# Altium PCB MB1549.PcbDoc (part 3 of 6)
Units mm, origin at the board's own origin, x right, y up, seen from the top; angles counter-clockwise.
Board outline 70 x 133.34 mm, 6 copper layers (Top Layer, Signal Layer 1, Signal Layer 2, Signal Layer 3, Signal Layer 4, Bottom Layer), stack 1.57 mm thick; 289 components, 250 nets, 1288 pads, 875 vias.
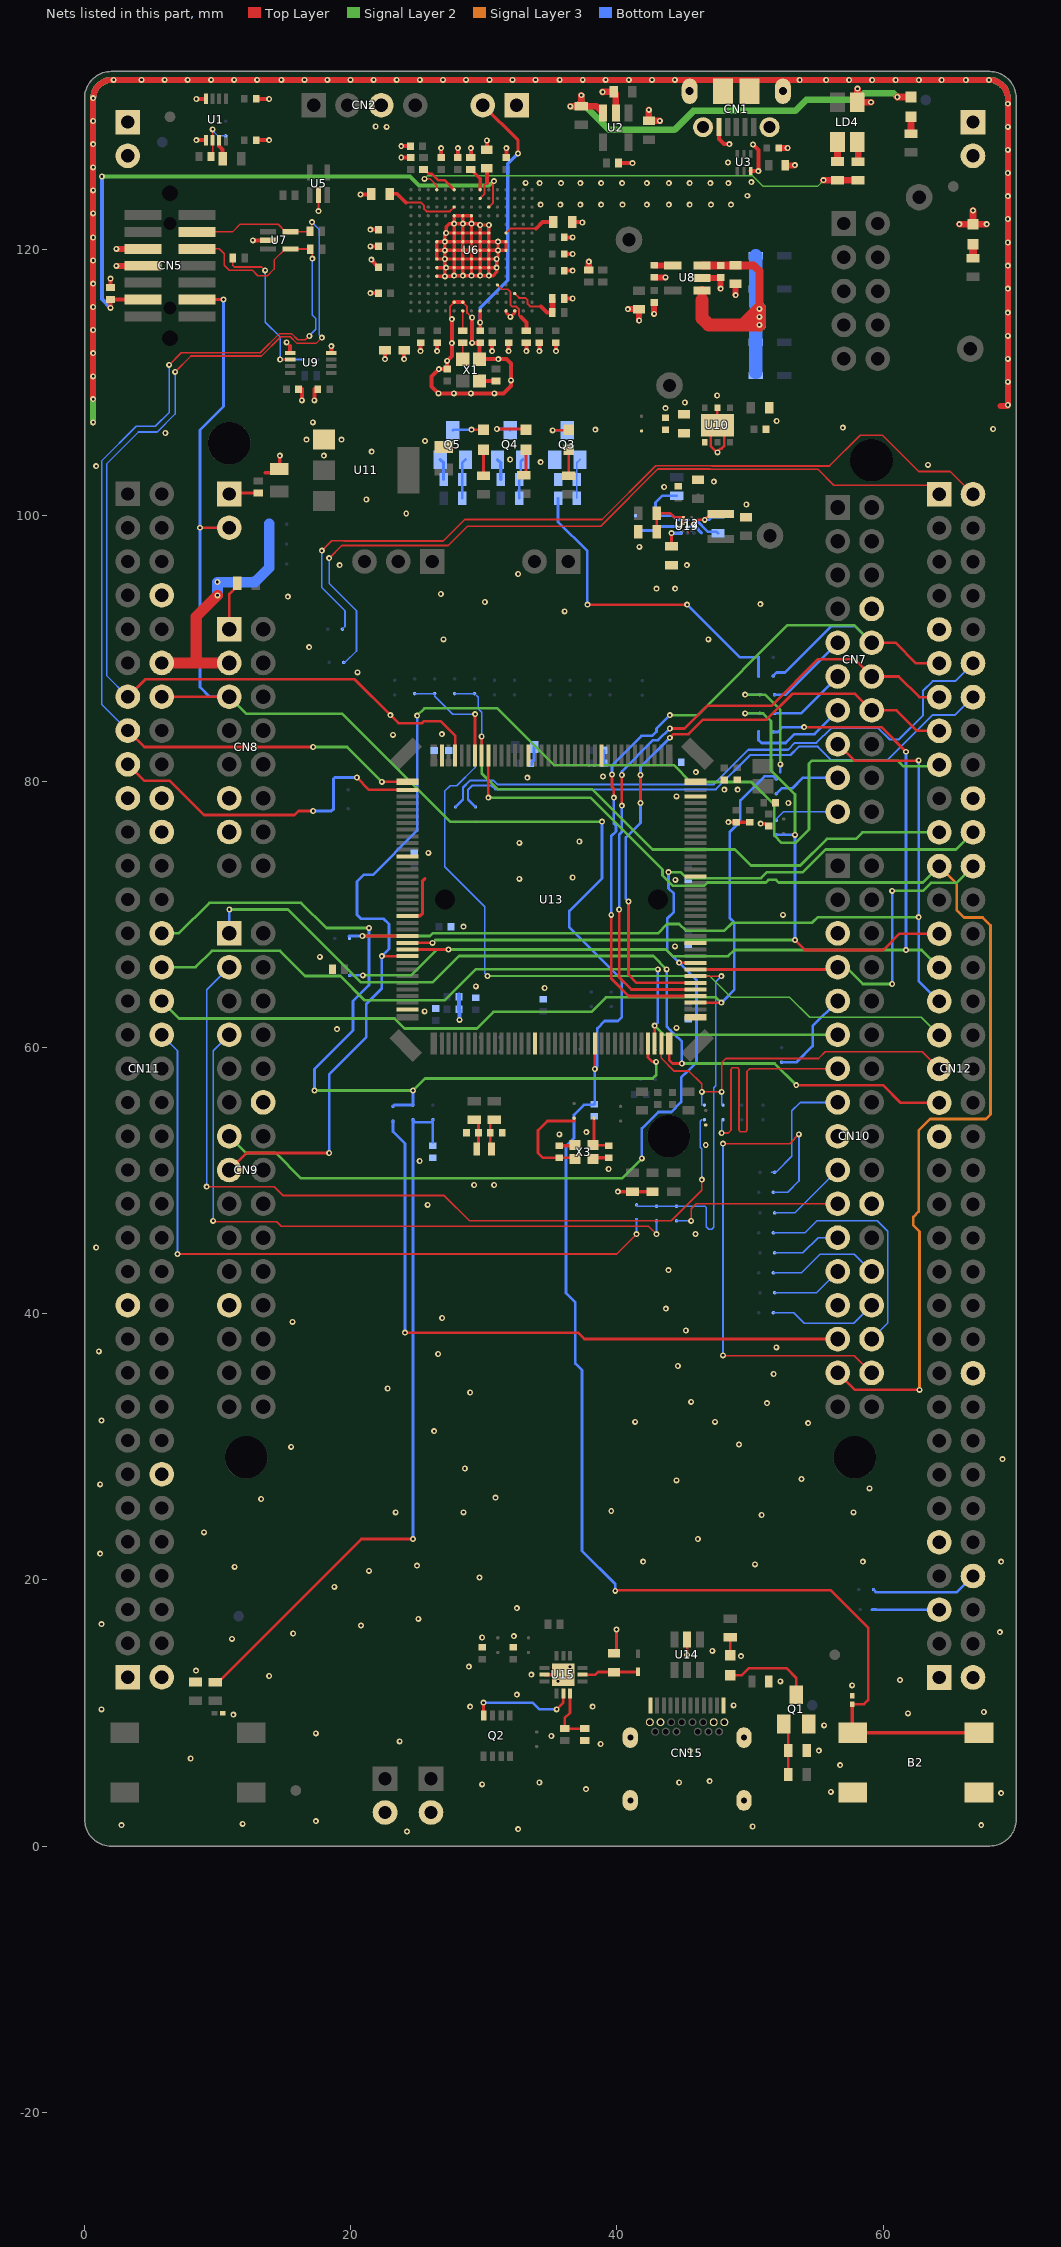
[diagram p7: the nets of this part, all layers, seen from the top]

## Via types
v1: diameter 0.45, hole 0.2, Top Layer to Bottom Layer, tented both sides, 875 vias

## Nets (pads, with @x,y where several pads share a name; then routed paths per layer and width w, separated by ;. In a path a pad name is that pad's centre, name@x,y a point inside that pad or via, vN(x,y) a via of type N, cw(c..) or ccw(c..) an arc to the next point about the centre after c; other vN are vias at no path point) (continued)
GND: B2.3 B2.4 C1.1 C2.1 C3.1 C4.2 C5.1 C6.1 C7.1 C8.1 C9.1 C10.1 C11.1 C12.1 C13.1 C14.1 C15.1 C16.1 C17.1 C18.1 C19.1 C20.1 C21.1 C22.1 C23.1 C24.1 C25.1 C26.1 C27.1 C28.1 C29.1 C30.1 C31.1 C32.1 C33.1 C34.1 C35.1 C36.2 C37.1 C38.1 C39.1 C40.1 C41.1 C42.1 C43.1 C44.1 C45.1 C46.1 C47.1 C48.1 C49.1 C50.1 C51.1 C52.1 C57.2 C58.2 C59.2 C60.2 C61.1 C62.1 C63.1 C64.1 C66.1 C67.1 C68.1 C69.1 C70.1 C71.1 C72.1 C73.1 C74.1 C75.1 C76.1 C77.1 C78.1 C79.1 C80.1 C81.1 C82.1 C83.1 C84.1 CN1.5 CN1.6 CN1.7 CN1.8 CN1.9 CN1.10 CN1.11 CN2.3 CN3.1 CN3.2 CN4.1 CN4.2 CN5.5 CN5.7 CN7.8 CN8.11 CN8.13 CN9.12 CN9.23 CN10.5 CN10.17 CN10.22 CN10.27 CN11.8 CN11.19 CN11.20 CN11.22 CN11.49 CN11.60 CN12.9 CN12.20 CN12.39 CN12.54 CN12.63 CN13.1 CN13.2 CN14.1 CN14.2 CN15.A1 CN15.A12 CN15.B1 CN15.B12 CN15.SH1 CN15.SH2 CN15.SH3 CN15.SH4 JP1.1 JP7.2 JP8.2 LD4.1 LD5.2 Q1.2 Q3.2 Q4.2 Q5.2 R6.1 R9.2 R15.1 R17.1 R18.2 R21.1 R28.2 R29.2 R31.2 R34.1 R38.1 R41.1 R42.1 R45.1 R46.1 R47.1 SB7.1 SB15.1 U1.4 U1.5 U2.2 U3.3 U4.2 U5.2 U6.D5 U6.D6 U6.D7 U6.D8 U6.D9 U6.F2 U6.F6 U6.F7 U6.F8 U6.F9 U6.F10 U6.F12 U6.G2 U6.G6 U6.G7 U6.G8 U6.G9 U6.G10 U6.G12 U6.H6 U6.H7 U6.H8 U6.H9 U6.H10 U6.H12 U6.J6 U6.J7 U6.J8 U6.J9 U6.J10 U6.K6 U6.K7 U6.K8 U6.K9 U6.K10 U6.M1 U6.M8 U6.M9 U6.N1 U7.2 U8.2 U9.4 U9.5 U10.2 U10.EP U11.1 U12.D2 U13.16 U13.37 U13.48 U13.58 U13.70 U13.72 U13.83 U13.94 U13.107 U13.120 U13.129 U13.143 U14.2 U15.2 U15.13 U16.2 U17.2 U18.2 U19.B1 U19.B2 X1.2 X3.2 X3.4 | length 573.6
  Top Layer w0.12: v1(17.575,122.85) U5.2@17.575,124.05 ; 45.307,98.662 U12.D2@45.307,99.106
  Top Layer w0.15: v1@27.129,118.604 27.148,118.623 v1@27.15,118.625 ; v1(27.591,114.729) 27.441,114.879 27.441,115.679 U6.F2@27.766,116.004 ; U6.G2@28.416,116.004 28.741,115.679 28.741,115.204 29.091,114.854 v1(29.116,114.854)
  Top Layer w0.2: v1(45.27,14.381) U14.2@45.27,15.531 U14.2@45.27,14.986 ; U10.2@47.545,108.071 U10.EP@47.545,106.771 ; v1(47.55,104.725) v1@47.505,104.725 ; v1@47.505,104.725 47.781,105.001 47.861,105.001 48.05,105.19 48.05,106.266 U10.EP@47.545,106.771 ; v1@47.505,104.725 47.05,105.18 47.05,106.276 U10.EP@47.545,106.771
  Top Layer w0.25: 13.57,103.181 14.343,103.181 14.67,103.508 v1(14.67,104.481) ; U13.129@24.462,69.871 24.487,69.896 25.224,69.896 25.382,70.055 25.382,72.507 25.575,72.7 ; U6.D5@26.466,117.954 v1(27.066,117.954) ; U6.D6@26.466,118.604 v1@27.129,118.604 ; U6.M1@31.666,115.354 31.666,115.229 v1(31.991,114.904) 32.316,115.229 U6.N1@32.316,115.354 ; U15.2@34.545,12.881 U15.13@35.97,12.881 ; C59.2@35.67,52.631 36.82,52.631 X3.4@36.87,52.681 ; X3.2@38.17,51.681 38.22,51.731 C60.2@39.37,51.731 ; C64.1@39.77,14.481 39.97,14.681 v1(39.97,16.281) ; v1(40.07,49.181) R34.1@41.17,49.181 C61.1@42.67,49.181 ; v1(48.373,76.942) 48.96,76.942 C50.1@48.97,76.931 C51.1@49.97,76.931 ; v1(50.801,76.829) 51.121,76.829 51.3,76.65 C52.1@51.35,76.65 ; U6.D8@26.466,119.904 U6.D9@26.466,120.554 v1(27.066,120.554) ; U6.D8@26.466,119.904 U6.D7@26.466,119.254 v1(27.066,119.254) ; U6.D8@26.466,119.904 v1(27.066,119.904) ; v1(27.066,117.954) 27.716,117.954 v1(27.766,118.004) ; v1(27.066,117.954) 27.066,118.504 v1(27.166,118.604) ; v1(27.066,119.254) 27.066,118.704 27.148,118.623 v1(27.166,118.604) ; v1(27.066,119.254) v1(27.066,119.904) ; v1(27.066,119.254) U6.F7@27.766,119.254 ; v1(27.066,119.904) v1(27.066,120.554) ; v1(27.066,119.904) U6.F8@27.766,119.904 ; v1(27.066,120.554) 27.066,121.104 v1(27.166,121.204) ; v1(27.066,120.554) U6.F9@27.766,120.554 ; v1(27.166,118.604) U6.F6@27.766,118.604 ; v1(27.166,121.204) 27.166,121.679 27.391,121.904 v1(27.766,121.904) ; v1(27.166,121.204) U6.F10@27.766,121.204 ; v1(27.766,118.004) v1(28.416,118.004) ; v1(27.766,118.004) U6.F6@27.766,118.604 ; U6.F6@27.766,118.604 U6.G6@28.416,118.604 ; U6.F6@27.766,118.604 U6.F7@27.766,119.254 ; U6.F7@27.766,119.254 U6.G7@28.416,119.254 ; U6.F7@27.766,119.254 U6.F8@27.766,119.904 ; U6.F8@27.766,119.904 U6.G8@28.416,119.904 ; U6.F8@27.766,119.904 U6.F9@27.766,120.554 ; U6.F9@27.766,120.554 U6.G9@28.416,120.554 ; U6.F9@27.766,120.554 U6.F10@27.766,121.204 ; U6.F10@27.766,121.204 v1(27.766,121.904) ; U6.F10@27.766,121.204 U6.G10@28.416,121.204 ; v1(27.766,121.904) v1(28.416,121.904) ; v1(27.766,121.904) U6.F12@27.766,122.504 U6.G12@28.416,122.504 ; v1(28.416,118.004) v1(29.066,118.004) ; v1(28.416,118.004) U6.G6@28.416,118.604 ; U6.G6@28.416,118.604 U6.G7@28.416,119.254 ; U6.G6@28.416,118.604 U6.H6@29.066,118.604 ; U6.G7@28.416,119.254 U6.G8@28.416,119.904 ; U6.G7@28.416,119.254 U6.H7@29.066,119.254 ; U6.G8@28.416,119.904 U6.G9@28.416,120.554 ; U6.G8@28.416,119.904 U6.H8@29.066,119.904 ; U6.G9@28.416,120.554 U6.G10@28.416,121.204 ; U6.G9@28.416,120.554 U6.H9@29.066,120.554 ; U6.G10@28.416,121.204 v1(28.416,121.904) ; U6.G10@28.416,121.204 U6.H10@29.066,121.204 ; v1(28.416,121.904) v1(29.066,121.904) ; v1(28.416,121.904) U6.G12@28.416,122.504 ; U6.G12@28.416,122.504 U6.H12@29.066,122.504 v1(29.066,121.904) ; v1(29.066,118.004) v1(29.716,118.004) ; v1(29.066,118.004) U6.H6@29.066,118.604 ; U6.H6@29.066,118.604 U6.H7@29.066,119.254 ; U6.H6@29.066,118.604 U6.J6@29.716,118.604 ; U6.H7@29.066,119.254 U6.H8@29.066,119.904 ; U6.H7@29.066,119.254 U6.J7@29.716,119.254 ; U6.H8@29.066,119.904 U6.H9@29.066,120.554 ; U6.H8@29.066,119.904 U6.J8@29.716,119.904 ; U6.H9@29.066,120.554 U6.H10@29.066,121.204 ; U6.H9@29.066,120.554 U6.J9@29.716,120.554 ; U6.H10@29.066,121.204 v1(29.066,121.904) ; U6.H10@29.066,121.204 U6.J10@29.716,121.204 ; v1(29.066,121.904) 29.616,121.904 v1(29.716,121.804) ; v1(29.716,118.004) v1(30.366,118.004) ; v1(29.716,118.004) U6.J6@29.716,118.604 ; U6.J6@29.716,118.604 U6.J7@29.716,119.254 ; U6.J6@29.716,118.604 U6.K6@30.366,118.604 ; U6.J7@29.716,119.254 U6.J8@29.716,119.904 ; U6.J7@29.716,119.254 U6.K7@30.366,119.254 ; U6.J8@29.716,119.904 U6.K8@30.366,119.904 ; U6.J8@29.716,119.904 U6.J9@29.716,120.554 ; U6.J9@29.716,120.554 U6.K9@30.366,120.554 ; U6.J9@29.716,120.554 U6.J10@29.716,121.204 ; U6.J10@29.716,121.204 U6.K10@30.366,121.204 ; U6.J10@29.716,121.204 v1(29.716,121.804) ; v1(29.716,121.804) v1(30.366,121.804) U6.K10@30.366,121.204 ; v1(30.366,118.004) 30.691,118.004 30.966,118.279 v1(30.966,118.604) ; v1(30.366,118.004) U6.K6@30.366,118.604 ; U6.K6@30.366,118.604 U6.K7@30.366,119.254 ; U6.K6@30.366,118.604 v1(30.966,118.604) ; U6.K7@30.366,119.254 U6.K8@30.366,119.904 ; U6.K7@30.366,119.254 v1(30.966,119.254) ; U6.K8@30.366,119.904 v1(31.066,119.904) ; U6.K8@30.366,119.904 U6.K9@30.366,120.554 ; U6.K9@30.366,120.554 v1(31.066,120.554) ; U6.K9@30.366,120.554 U6.K10@30.366,121.204 ; v1(30.966,118.604) v1(30.966,119.254) ; v1(30.966,119.254) 31.066,119.354 v1(31.066,119.904) ; v1(31.066,119.904) v1(31.066,120.554) ; v1(31.066,119.904) U6.M8@31.666,119.904 U6.M9@31.666,120.554 v1(31.066,120.554)
  Top Layer w0.3: R17.1@1.941,117.104 v1(1.941,117.779) ; v1(8.391,128.179) U1.5@9.116,128.179 ; v1(8.391,131.279) U1.4@9.116,131.279 ; v1(12.641,120.654) U7.2@13.766,120.654 ; C4.2@13.141,128.179 v1(13.866,128.179) ; C2.1@13.141,131.279 v1(13.866,131.279) ; U9.5@15.441,112.204 15.441,112.729 ; v1(16.316,108.629) C36.2@16.316,109.479 ; v1(17.266,108.629) C37.1@17.266,109.479 ; U9.4@18.541,112.204 v1(18.541,112.704) ; v1@20.791,124.104 C12.1@21.416,124.104 ; v1(21.466,116.679) C25.1@22.091,116.679 ; v1(21.466,120.204) C16.1@22.091,120.204 ; v1(21.466,121.454) C14.1@22.091,121.454 ; v1(21.541,119.204) 21.541,119.179 C21.1@22.091,118.629 ; v1(22.566,111.729) C33.1@22.566,112.379 ; v1(23.791,126.879) C8.1@24.491,126.879 ; v1(23.791,127.729) C5.1@24.491,127.729 ; v1(24.016,111.729) C34.1@24.016,112.379 ; v1(25.241,112.329) C26.1@25.241,112.954 ; v1(26.491,112.329) C27.1@26.491,112.954 ; C9.1@26.791,126.879 v1(26.791,127.579) ; v1(27.591,114.729) v1(27.591,112.929) 27.591,111.954 v1(27.241,111.604) C35.1@27.241,110.979 v1(26.616,110.979) 26.066,110.429 26.066,109.679 v1(26.591,109.154) v1(27.741,109.154) v1(29.016,109.154) v1(30.791,109.154) 31.491,109.154 32.041,109.704 v1(32.041,110.129) 32.036,110.134 32.036,111.384 31.691,111.729 v1(31.091,111.729) X1.2@29.666,111.729 29.666,112.904 C28.1@29.716,112.954 v1(29.116,112.954) v1(29.116,114.854) ; U6.F2@27.766,116.004 U6.G2@28.416,116.004 ; C10.1@28.041,126.879 v1(28.041,127.579) ; R6.1@29.016,126.879 v1(29.016,127.579) ; C7.1@30.216,127.454 v1(30.216,128.154) ; v1(30.616,112.329) C29.1@30.616,112.954 ; C11.1@31.691,126.879 v1(31.691,127.579) ; v1(31.866,112.329) C30.1@31.866,112.954 ; v1(33.191,112.329) R21.1@33.191,112.954 ; v1(34.166,112.329) C31.1@34.166,112.954 ; v1(35.416,112.329) C32.1@35.416,112.954 ; R18.2@36.041,116.279 v1(36.666,116.279) ; C22.1@36.041,118.379 v1(36.666,118.379) ; C17.1@36.041,119.629 v1(36.666,119.629) ; C15.1@36.041,120.879 v1(36.666,120.879) ; C13.1@36.625,122.025 v1@37.375,122.025 ; R9.2@40.373,126.459 41.161,126.459 v1(41.166,126.454) ; CN1.5@47.666,129.158 47.666,128.254 48.041,127.879 v1(48.441,127.879) ; U3.3@50.041,125.854 v1(50.616,125.854) 50.616,127.454 v1(50.216,127.854)
  Top Layer w0.45: v1(0.641,108.716) v1(0.641,110.441) v1(0.641,112.179) v1(0.641,113.917) v1(0.641,115.642) v1(0.641,117.404) v1(0.641,119.141) v1(0.641,120.866) v1(0.641,122.679) v1(0.641,124.416) v1(0.641,126.142) v1(0.641,127.879) v1(0.641,129.616) 0.641,131.294 cw(c2.062,131.294) 2.062,132.715 v1(23.441,132.716) CN1.8@45.441,132.715 ; v1(2.381,118.744) CN5.7@4.389,118.744 ; v1(2.381,120.014) CN5.5@4.389,120.014 ; v1(40.816,115.479) C23.1@41.666,115.479 v1(41.666,114.629) ; v1(42.791,115.129) C24.1@42.791,115.979 ; C19.1@42.791,117.879 v1(43.641,117.879) ; CN1.8@45.466,131.858 45.466,132.69 CN1.8@45.441,132.715 ; U8.2@46.391,117.829 47.752,117.829 47.794,117.871 v1(47.794,117.021) ; v1(48.916,116.529) C18.1@48.916,117.379 ; C6.1@52.149,127.593 v1(52.83,127.593) ; U4.2@52.649,126.293 53.355,126.293 v1(53.366,126.304) ; 68.825,108.2 v1@69.35,108.2 ; v1(69.366,108.279) v1(69.366,110.016) v1(69.366,111.754) v1(69.366,113.479) v1(69.366,115.216) v1(69.366,117.029) v1(69.366,118.754) v1(69.366,120.491) v1(69.366,122.254) v1(69.366,123.979) v1(69.366,125.716) v1(69.366,127.454) v1(69.366,129.179) v1(69.366,130.916) 69.366,131.269 69.375,131.278 ccw(c67.949,131.278) v1(67.949,132.704) v1(66.212,132.704) v1(64.399,132.704) v1(62.674,132.704) v1(60.937,132.704) v1(59.174,132.704) v1(57.449,132.704) v1(55.712,132.704) v1(53.729,132.704) 52.352,132.704 52.341,132.715 CN1.8@45.441,132.715
  Top Layer w0.5: R15.1@37.891,118.429 v1(37.891,119.054) ; v1(38.923,131.804) 38.907,131.82 C1.1@39.748,131.82 39.916,131.652 U2.2@39.916,130.214 ; v1(42.391,130.454) 42.396,130.449 C3.1@42.396,129.627 43.218,129.627 v1(43.223,129.632) ; v1(58.066,132.054) LD4.1@58.066,131.029 v1(59.091,131.029) ; v1(65.721,121.869) LD5.2@66.746,121.869 ; v1(66.746,122.894) LD5.2@66.746,121.869 ; v1(67.771,121.869) LD5.2@66.746,121.869
  Signal Layer 2 w0.45: v1(0.641,106.979) v1(0.641,108.716) v1(0.641,110.441) v1(0.641,112.179) v1(0.641,113.917) v1(0.641,115.642) v1(0.641,117.404) v1(0.641,119.141) v1(0.641,120.866) v1(0.641,122.679) v1(0.641,124.416) v1(0.641,126.142) v1(0.641,127.879) v1(0.641,129.616) 0.641,131.294 cw(c2.062,131.294) 2.062,132.715 v1(6.016,132.716) v1(18.241,132.716) v1(35.691,132.716) CN1.8@45.441,132.715 ; CN1.8@45.466,131.858 45.466,132.69 CN1.8@45.441,132.715 ; 69.375,131.278 ccw(c67.949,131.278) v1(67.949,132.704) v1(66.212,132.704) v1(64.399,132.704) v1(62.674,132.704) v1(60.937,132.704) v1(59.174,132.704) v1(57.449,132.704) v1(55.712,132.704) v1(53.729,132.704) 52.352,132.704 52.341,132.715 CN1.8@45.441,132.715
  Signal Layer 3 w0.45: v1(0.641,108.716) v1(0.641,110.441) v1(0.641,112.179) v1(0.641,113.917) v1(0.641,115.642) v1(0.641,117.404) v1(0.641,119.141) v1(0.641,120.866) v1(0.641,122.679) v1(0.641,124.416) v1(0.641,126.142) v1(0.641,127.879) v1(0.641,129.616) 0.641,131.294 cw(c2.062,131.294) 2.062,132.715 v1(4.279,132.716) v1(21.716,132.716) v1(35.691,132.716) v1(44.354,132.716) CN1.8@45.441,132.715 ; CN1.8@45.466,131.858 45.466,132.69 CN1.8@45.441,132.715 ; 69.375,131.278 ccw(c67.949,131.278) v1(67.949,132.704) v1(66.212,132.704) v1(64.399,132.704) v1(62.674,132.704) v1(60.937,132.704) v1(59.174,132.704) v1(57.449,132.704) v1(55.712,132.704) v1(53.729,132.704) 52.352,132.704 52.341,132.715 CN1.8@45.441,132.715
  Bottom Layer w0.25: Q5.2@26.72,104.181 26.97,103.931 R47.1@26.97,102.681 ; C82.1@28.12,62.881 C82.1@28.17,62.831 ; Q4.2@31.02,104.181 31.27,103.931 R46.1@31.27,102.681 ; C72.1@33.604,81.297 C72.1@33.52,81.381 33.77,81.631 C66.1@33.77,82.581 ; C67.1@39.025,82.325 39.02,82.32 C71.1@39.02,81.381 C71.1@39.104,81.297 ; U19.B2@45.295,99.156 U19.B1@45.795,99.156 45.872,99.156 46.345,98.683
  Bottom Layer w0.3: C82.1@28.12,62.881 C78.1@28.12,63.981 ; v1(28.17,62.081) C82.1@28.17,62.831
  Bottom Layer w0.45: v1(0.641,108.716) v1(0.641,110.441) v1(0.641,112.179) v1(0.641,113.917) v1(0.641,115.642) v1(0.641,117.404) v1(0.641,119.141) v1(0.641,120.866) v1(0.641,122.679) v1(0.641,124.416) v1(0.641,126.142) v1(0.641,127.879) v1(0.641,129.616) 0.641,131.294 cw(c2.062,131.294) 2.062,132.715 v1(18.241,132.716) CN1.8@45.441,132.715 ; CN1.8@45.466,131.858 45.466,132.69 CN1.8@45.441,132.715 ; 69.375,131.278 ccw(c67.949,131.278) v1(67.949,132.704) v1(66.212,132.704) v1(64.399,132.704) v1(62.674,132.704) v1(60.937,132.704) v1(59.174,132.704) v1(57.449,132.704) v1(55.712,132.704) v1(53.729,132.704) 52.352,132.704 52.341,132.715 CN1.8@45.441,132.715
  other v1: 24.225,1.1 32.57,1.281 50.195,1.481 2.77,1.581 67.37,1.581 11.87,1.681 17.37,1.881 68.87,3.981 56.07,4.081 37.67,4.281 29.87,4.644 34.17,4.781 44.67,4.781 46.97,4.881 56.77,6.081 7.97,6.581 45.47,7.181 55.17,7.181 38.77,7.681 23.67,7.881 35.07,8.281 17.37,8.481 55.57,9.081 11.17,9.881 61.87,9.981 67.57,10.081 1.27,10.281 28.97,10.481 38.17,10.481 48.77,10.581 32.47,11.381 57.67,12.081 35.57,12.381 52.27,12.381 61.27,12.481 13.87,12.781 33.57,12.881 8.37,13.181 28.87,13.481 36.47,13.481 49.322,14.281 47.17,14.681 11.07,15.581 29.87,15.681 32.245,15.781 15.67,15.981 68.77,16.081 20.77,16.581 1.27,16.681 25.07,17.081 32.47,17.881 18.77,19.481 29.67,20.181 21.37,20.681 11.27,20.981 24.97,21.081 50.37,21.181 41.97,21.381 58.47,21.381 68.87,21.381 1.17,21.981 46.07,23.081 8.97,23.581 50.87,24.881 23.37,25.081 28.47,25.081 57.77,25.081 39.57,25.181 13.27,26.081 30.87,26.181 58.97,26.881 1.17,27.181 44.47,27.481 53.87,27.581 28.57,28.381 68.97,29.081 15.525,30 49.17,30.181 26.27,31.181 54.37,31.781 41.37,31.881 47.37,31.881 1.27,31.981 51.27,33.281 45.57,33.381 28.97,34.081 22.77,34.381 51.77,35.481 44.57,36.081 26.57,36.981 1.07,37.181 51.97,37.481 45.175,38.75 15.625,39.4 26.87,39.681 43.67,40.381 43.87,43.281 0.87,44.981 45.9,46 25.77,48.181 29.27,49.681 30.77,49.681 39.37,50.881 25.17,51.481 46.67,52.681 35.67,53.481 37.7,53.65 18.97,61.381 44.47,61.481 25.55,62.725 34.57,64.481 29.4,64.6 17.675,66.825 44.362,67.604 28.47,69.081 52.47,69.981 44.387,72.604 32.67,72.681 36.67,72.781 25.827,74.638 32.67,75.381 37.17,75.481 52.87,78.381 44.47,78.881 48.07,79.381 49.07,79.381 33.27,80.281 38.95,80.375 45.925,80.7 23.17,83.496 26.837,83.548 20.5,88.2 16.87,90.081 26.97,90.681 46.87,90.681 36.07,92.781 50.77,93.321 30.07,93.481 15.27,93.881 26.77,94.081 42.97,94.481 44.37,94.481 32.57,95.581 19.17,96.247 45.25,96.25 41.675,97.625 24.167,100.131 49.725,100.8 21.17,101.181 43.55,102.125 47.275,102.525 0.87,103.681 63.37,103.781 34.27,103.981 31.97,104.181 17.97,104.481 21.57,104.781 25.57,105.581 16.67,105.681 19.307,105.681 6.07,106.181 38.37,106.431 68.27,106.481 56.97,106.581 17.15,106.975 52,107.075 43.65,108.05 45.1,108.475 47.525,109 15.18,112.995 37.4,122 34.266,123.329 35.741,123.329 37.241,123.329 38.816,123.329 40.416,123.329 42.241,123.329 43.891,123.329 45.466,123.329 47.066,123.329 48.566,123.329 49.791,124.004 20.725,124.1 34.191,124.954 35.791,124.954 37.241,124.954 38.816,124.954 40.391,124.954 42.241,124.954 43.891,124.954 45.466,124.954 47.016,124.954 48.366,124.954 33.141,124.979 50.091,125.029 48.341,126.504 22.691,129.179 21.866,129.204 0.641,131.342 2.178,132.716 7.741,132.716 9.503,132.716 11.241,132.716 12.966,132.716 14.778,132.716 16.516,132.716 19.978,132.716 25.191,132.716 26.929,132.716 28.654,132.716 30.416,132.716 32.153,132.716 33.878,132.716 37.429,132.716 39.154,132.716 40.891,132.716 42.628,132.716
GNDDetect: CN5.11 R17.2 U6.K13 | length 45.2
  Top Layer w0.15: U6.K13@30.366,123.154 30.691,123.479 30.691,125.029 v1(30.766,125.104)
  Top Layer w0.3: v1(1.941,115.579) R17.2@1.941,116.204 CN5.11@4.389,116.204
  Signal Layer 2 w0.3: v1(1.291,125.454) 24.466,125.454 25.136,124.784 30.396,124.784 30.741,125.129 v1(30.766,125.104)
  Bottom Layer w0.3: v1(1.291,125.454) 1.291,116.229 v1(1.941,115.579)
IOREF: CN8.3 CN11.12 SB16.2 SB17.2 SB18.2 | length 19.4
  Top Layer w0.8: CN11.12@5.79,88.901 8.37,88.901 ; v1(9.989,93.981) 8.37,92.362 8.37,88.901 ; CN8.3@10.87,88.901 8.37,88.901
  Bottom Layer w0.8: v1(9.989,93.981) 9.989,94.962 12.782,94.962 13.875,96.055 13.875,99.35
  other v1: 9.97,94.981
LED_STLK: R7.2 R8.2 U6.D15 | length 34.7
  Top Layer w0.12: v1(25.541,125.279) 25.952,125.279 26.466,124.764 U6.D15@26.466,124.454 ; R7.2@56.564,125.179 R7.2@56.566,125.177 ; R8.2@58.091,125.177 R8.2@58.116,125.152
  Top Layer w0.5: v1(55.516,125.179) R7.2@56.564,125.179 ; R7.2@56.566,125.177 R8.2@58.091,125.177
  Signal Layer 2 w0.12: v1(25.541,125.279) 25.771,125.509 50.184,125.509 50.989,124.704 55.066,124.704 55.528,125.166 55.541,125.179 v1(55.516,125.179)
NetC7_2: C7.2 U6.J14 | length 2.5
  Top Layer w0.15: U6.J14@29.716,123.804 30.036,124.124 30.036,124.774 30.216,124.954
  Top Layer w0.3: 30.216,124.954 C7.2@30.216,126.054
NetC12_2: C12.2 U6.F13 | length 5.6
  Top Layer w0.15: 24.141,123.479 24.146,123.484 25.289,123.484 25.496,123.277 25.496,123.021 25.694,122.824 27.436,122.824 U6.F13@27.766,123.154
  Top Layer w0.3: C12.2@22.975,124.15 22.979,124.154 23.466,124.154 24.141,123.479
NetC13_2: C13.2 U6.M10 | length 3.8
  Top Layer w0.15: U6.M10@31.666,121.204 31.987,121.525 33.9,121.525
  Top Layer w0.3: 33.9,121.525 34.4,122.025 C13.2@35.1,122.025
NetC18_2: C18.2 C20.2 D2.2 D3.2 D4.2 D5.2 U8.1 U8.3 | length 28.2
  Top Layer w0.45: C20.2@47.785,118.779 C20.2@47.794,118.771 ; C18.2@48.907,118.771 C18.2@48.916,118.779
  Top Layer w0.6: U8.3@46.391,118.779 C20.2@47.785,118.779 ; C20.2@47.794,118.77 C18.2@48.907,118.771 ; C18.2@48.916,118.779 50.266,118.779 50.691,118.354 v1(50.691,115.504)
  Top Layer w0.7: 46.391,116.154 U8.1@46.391,116.879
  Top Layer w1: 46.391,116.154 46.391,114.804 46.896,114.299 49.486,114.299 ; 49.486,114.299 v1(50.691,114.299) v1(50.691,114.904) v1(50.691,115.504) 50.391,115.204 49.486,114.299
  Signal Layer 2 w1: v1(50.691,114.299) v1(50.691,114.904) v1(50.691,115.504)
  Signal Layer 3 w1: v1(50.691,114.299) v1(50.691,114.904) v1(50.691,115.504)
  Bottom Layer w1: D5.2@50.43,110.725 D4.2@50.43,113 50.43,114.038 v1(50.691,114.299) v1(50.691,114.904) v1(50.691,115.504) 50.43,115.765 D3.2@50.43,117 D2.2@50.43,119.5
NetC19_2: C19.2 U8.4 | length 1.4
  Top Layer w0.45: C19.2@42.791,118.779 U8.4@44.191,118.779
NetC28_2: C28.2 JP1.2 U6.J1 | length 20.1
  Top Layer w0.25: C28.2@29.716,113.854 v1(29.716,114.479) U6.J1@29.716,115.354 ; JP1.2@29.916,130.809 32.566,128.159 v1(32.566,127.179)
  Bottom Layer w0.25: v1(29.716,114.479) 29.716,115.579 31.791,117.654 31.791,126.404 v1(32.566,127.179)
NetC39_2: C39.2 C40.2 SB1.1 U10.4
NetC64_2: C64.2 D1.2 U15.8 | length 4.3
  Top Layer w0.2: U15.8@37.395,12.881 38.37,12.881 38.57,13.081 C64.2@39.77,13.081 41.545,13.081 D1.2@41.57,13.106
NetC84_2: C84.2 R39.1 SB58.1 SB59.1 | length 54.1
  Top Layer w0.2: R39.1@9.82,12.331 10.045,12.331 20.795,23.081 v1(24.67,23.081)
  Bottom Layer w0.2: v1(24.67,23.081) SB59.1@24.67,54.581 24.87,54.381 26.17,54.381 ; C84.2@26.17,52.881 26.17,54.381 ; SB58.1@26.17,54.581 26.17,54.381
NetCN7_9: CN7.9 SB35.2 | length 6.4
  Bottom Layer w0.2: SB35.2@51.837,86.518 52.683,86.518 CN7.9@56.59,90.425
NetCN7_11: CN7.11 SB36.2 | length 5.9
  Bottom Layer w0.2: SB36.2@51.837,85.118 53.823,85.118 CN7.11@56.59,87.885
NetCN7_13: CN7.13 SB37.2 | length 7.7
  Bottom Layer w0.2: SB37.2@50.637,83.718 50.637,83.101 50.856,82.881 52.67,82.881 53.343,83.554 54.843,83.554 CN7.13@56.57,85.281 ; CN7.13@56.57,85.345 CN7.13@56.59,85.345
NetCN7_17: CN7.17 SB38.2 | length 5.1
  Bottom Layer w0.2: SB38.2@51.97,79.081 52.37,79.481 53.17,79.481 53.954,80.265 CN7.17@56.59,80.265
NetCN7_19: CN7.19 SB43.2 | length 4.9
  Bottom Layer w0.127: SB43.2@51.97,77.081 51.97,77.181 52.514,77.725 CN7.19@56.59,77.725
NetCN8_1: CN8.1 R30.1 | length 3.7
  Top Layer w0.2: CN8.1@10.87,91.441 10.87,94.081 11.47,94.681 R30.1@11.47,94.881
NetCN9_3: CN9.3 SB57.2 | length 61.8
  Top Layer w0.127: v1(9.17,49.551) 14.245,49.551 14.915,48.881 27.025,48.881 28.925,46.981 44.07,46.981 46.37,49.281 v1(46.37,50.081)
  Bottom Layer w0.127: v1(9.17,49.551) 9.17,64.341 CN9.3@10.87,66.041 ; v1(46.37,50.081) 46.37,52.394 46.254,52.509 46.254,54.466 46.37,54.581
NetCN9_7: CN9.7 SB64.2 | length 49.2
  Top Layer w0.127: v1(9.665,46.981) 9.737,46.91 14.442,46.91 14.77,46.581 42.371,46.581 v1(42.97,45.981)
  Bottom Layer w0.127: v1(9.665,46.981) 9.665,59.756 CN9.7@10.87,60.961 ; v1(42.97,45.981) SB64.2@42.97,46.981
NetCN10_9: CN10.9 SB53.2 | length 7
  Bottom Layer w0.2: SB53.2@52.37,58.9 53.475,58.9 54.7,60.125 54.7,61.611 CN10.9@56.59,63.501
NetCN10_13: CN10.13 SB56.2 | length 23.7
  Top Layer w0.127: v1(47.87,53.581) 48.37,53.581 48.57,53.781 48.57,58.281 48.57,58.381 48.67,58.481 49.07,58.481 49.17,58.381 49.17,53.781 49.27,53.681 49.67,53.681 49.77,53.781 49.77,58.221 49.97,58.421 CN10.13@56.59,58.421
  Bottom Layer w0.127: v1(47.87,53.581) SB56.2@47.87,54.581
NetCN10_15: CN10.15 SB61.2 | length 9.2
  Bottom Layer w0.127: 51.595,50.631 51.945,50.631 53.142,51.828 53.142,55.253 53.77,55.881 CN10.15@56.59,55.881
NetCN10_19: CN10.19 SB66.2 | length 6.1
  Bottom Layer w0.127: SB66.2@51.845,47.581 53.37,47.581 CN10.19@56.59,50.801
NetCN10_21: CN10.21 SB63.2 | length 13.2
  Top Layer w0.127: v1(45.57,46.981) 45.57,47.881 45.95,48.261 CN10.21@56.59,48.261
  Bottom Layer w0.127: SB63.2@44.47,46.981 v1(45.57,46.981)
NetCN10_23: CN10.23 SB68.2 | length 5.4
  Top Layer w0.127: CN10.23@56.59,45.511 CN10.23@56.59,45.721
  Bottom Layer w0.127: SB68.2@51.845,44.581 53.97,44.581 55.11,45.721 CN10.23@56.59,45.721
NetCN10_25: CN10.25 SB70.2 | length 5.4
  Bottom Layer w0.127: SB70.2@51.845,41.581 54.99,41.581 CN10.25@56.59,43.181
NetCN10_26: CN10.26 SB69.1 | length 8.5
  Bottom Layer w0.127: SB69.1@51.745,43.081 53.87,43.081 55.26,44.471 57.84,44.471 CN10.26@59.13,43.181
NetCN10_28: CN10.28 SB71.1 | length 8.3
  Bottom Layer w0.127: SB71.1@51.745,40.081 53.27,40.081 54.062,39.29 57.779,39.29 CN10.28@59.13,40.641
NetCN10_29: CN10.29 SB60.2 | length 49
  Top Layer w0.2: v1(24.07,38.581) 37.07,38.581 37.55,38.101 CN10.29@56.59,38.101
  Bottom Layer w0.2: SB60.2@23.17,54.481 23.17,53.681 24.07,52.781 v1(24.07,38.581)
NetCN10_30: CN10.30 SB67.1 | length 17.9
  Bottom Layer w0.127: SB67.1@51.745,46.081 54.133,46.081 55.033,46.981 59.551,46.981 60.335,46.197 60.335,39.306 CN10.30@59.13,38.101
NetCN10_32: CN10.32 SB62.1 | length 39.4
  Top Layer w0.127: v1(47.97,36.881) 48,36.851 57.84,36.851 CN10.32@59.13,35.561 ; v1(47.97,52.781) 52.97,52.781 v1(53.67,53.481)
  Bottom Layer w0.127: v1(47.97,36.881) v1(47.97,52.781) ; SB62.1@51.745,49.131 52.82,49.131 53.67,49.981 v1(53.67,53.481)
NetCN11_34: CN11.34 SB65.1 | length 53.2
  Top Layer w0.127: v1(6.979,44.49) 39.979,44.49 v1(41.47,45.981)
  Bottom Layer w0.127: CN11.34@5.79,60.961 6.979,59.773 v1(6.979,44.49) ; v1(41.47,45.981) SB65.1@41.47,47.081
NetCN12_1: CN12.1 SB22.2 | length 58.5
  Top Layer w0.127: v1(18.375,96.775) 19.325,97.725 27.314,97.725 28.77,99.181 38.781,99.181 43.08,103.48 46.992,103.48 47.022,103.45 55.1,103.45 56.3,102.25 63.536,102.25 CN12.1@64.21,101.576
  Bottom Layer w0.127: v1(18.375,96.775) 18.375,94.876 20.425,92.826 20.425,89.8 19.566,88.941 SB22.2@19.47,88.941
NetCN12_2: CN12.2 SB19.1 | length 61.1
  Top Layer w0.127: v1(17.825,97.332) 18.564,98.071 19.476,98.071 19.481,98.066 26.955,98.066 28.57,99.681 38.87,99.681 42.915,103.727 47.094,103.727 47.124,103.697 55.962,103.697 58.27,106.005 59.946,106.005 62.67,103.281 65.045,103.281 CN12.2@66.75,101.576
  Bottom Layer w0.127: v1(17.825,97.332) 17.825,94.575 19.57,92.83 19.57,91.641 SB19.1@19.37,91.441
NetCN12_66: CN12.66 SB72.1 | length 8.1
  Bottom Layer w0.2: SB72.1@59.27,19.281 59.48,19.071 65.525,19.071 CN12.66@66.75,20.296
NetCN12_67: CN12.67 SB73.2 | length 5.3
  Bottom Layer w0.2: SB73.2@59.37,17.781 59.17,17.781 59.145,17.756 CN12.67@64.21,17.756
NetJP2_1: JP2.1 R26.2 | length 2.2
  Top Layer w0.2: JP2.1@10.866,101.599 10.942,101.675 R26.2@13.05,101.675
NetL1_1: L1.1 R52.1 U12.C3 | length 3.7
  Top Layer w0.2: U12.C3@45.619,99.356 45.919,99.656 v1(46.595,99.656) 47.045,100.106 L1.1@47.795,100.106
  Bottom Layer w0.2: v1(46.595,99.656) 46.92,99.656 47.32,100.056 R52.1@47.595,100.056
NetLD1_1: LD1.1 R25.1 | length 1.9
  Top Layer w0.2: R25.1@36.37,103.181 LD1.1@36.37,104.931
  Top Layer w0.25: R25.1@36.37,103.181 R25.1@36.47,103.081
NetLD1_2: LD1.2 Q3.3 | length 2.3
  Top Layer w0.2: v1(35.17,106.381) 36.32,106.381 LD1.2@36.37,106.431
  Bottom Layer w0.2: v1(35.17,106.381) Q3.3@36.27,106.381
NetLD2_1: LD2.1 R23.2 | length 1.9
  Top Layer w0.2: R23.2@33.17,103.181 LD2.1@33.17,104.931
  Top Layer w0.25: R23.2@33.17,103.181 33.176,103.176 R23.2@33.27,103.081
NetLD2_2: LD2.2 Q4.3 | length 3.3
  Top Layer w0.2: v1(30.97,106.481) 33.12,106.481 LD2.2@33.17,106.431
  Bottom Layer w0.2: v1(30.97,106.481) 31.87,106.481 Q4.3@31.97,106.381
NetLD3_1: LD3.1 R24.2 | length 2.2
  Top Layer w0.2: R24.2@29.97,102.881 R24.2@29.97,102.981 LD3.1@29.97,104.931
  Top Layer w0.25: R24.2@29.97,102.881 R24.2@30.07,102.781
NetLD3_2: LD3.2 Q5.3 | length 2.3
  Top Layer w0.2: v1(29.07,106.431) LD3.2@29.97,106.431
  Bottom Layer w0.2: Q5.3@27.67,106.381 27.72,106.431 v1(29.07,106.431)
NetLD4_2: LD4.2 R8.1 | length 1.5
  Top Layer w0.5: LD4.2@58.066,128.029 58.116,127.979 R8.1@58.116,126.552
NetLD4_3: LD4.3 R7.1 | length 1.5
  Top Layer w0.5: R7.1@56.566,126.577 LD4.3@56.566,128.029
NetLD5_1: LD5.1 R14.1 | length 1
  Top Layer w0.6: R14.1@66.746,119.319 LD5.1@66.746,120.369
NetLD6_1: LD6.1 R2.1 | length 1.2
  Top Layer w0.5: R2.1@62.091,128.679 LD6.1@62.091,129.929
NetLD6_2: LD6.2 R1.1 U2.3 | length 31.9
  Top Layer w0.5: v1(36.498,130.724) 36.503,130.729 R1.1@37.325,130.729 ; v1(37.32,131.555) 37.325,131.55 R1.1@37.325,130.729 ; U2.3@38.966,130.214 38.451,130.729 R1.1@37.325,130.729 ; v1(61.066,131.429) LD6.2@62.091,131.429
  Signal Layer 2 w0.5: v1(36.498,130.724) 36.986,130.724 37.32,131.058 ; v1(37.32,131.555) 37.32,131.058 ; v1(61.066,131.429) 60.791,131.704 58.557,131.704 58.057,131.204 54.216,131.204 53.391,130.379 45.741,130.379 44.316,128.954 39.424,128.954 37.32,131.058
NetLD7_1: LD7.1 R36.2 | length 1.3
  Top Layer w0.2: LD7.1@48.52,14.331 R36.2@48.52,15.681
NetLD7_2: LD7.2 Q1.3 | length 6.7
  Top Layer w0.2: LD7.2@48.52,12.831 49.37,12.831 49.914,13.375 52.72,13.375 53.47,12.625 Q1.3@53.47,11.381
NetQ1_1: Q1.1 R42.2 R43.2 | length 3.9
  Top Layer w0.2: Q1.1@52.52,9.181 52.87,8.831 R42.2@52.87,7.181 R43.2@52.87,5.381
NetQ2_4: Q2.4 U15.5 | length 8.1
  Top Layer w0.2: Q2.4@29.97,9.781 29.97,9.806 v1(29.97,10.781) ; v1(35.47,10.281) 35.97,10.781 U15.5@35.97,11.456
  Bottom Layer w0.2: v1(29.97,10.781) 33.67,10.781 34.17,10.281 v1(35.47,10.281)
NetQ3_1: Q3.1 R45.2 R49.2 | length 3
  Bottom Layer w0.127: R49.2@36.97,101.281 R45.2@36.97,102.681 36.97,103.931 Q3.1@37.22,104.181
NetQ4_1: Q4.1 R46.2 R50.2 | length 3
  Bottom Layer w0.2: R50.2@32.67,101.281 R46.2@32.67,102.681 32.77,102.781 32.77,104.031 Q4.1@32.92,104.181
NetQ5_1: Q5.1 R47.2 R51.2 | length 3
  Bottom Layer w0.2: R51.2@28.37,101.281 R47.2@28.37,102.681 28.37,103.931 Q5.1@28.62,104.181
NetR3_2: R3.2 SB11.2 U1.6 | length 3.3
  Top Layer w0.12: R3.2@9.491,126.954 9.616,127.079 U1.6@9.616,128.179 v1(9.616,128.991)
  Bottom Layer w0.12: v1(9.616,128.991) 9.616,128.9 10.016,128.5 SB11.2@10.6,128.5
NetR4_1: R4.1 U1.7 | length 1.5
  Top Layer w0.3: U1.7@10.116,128.179 10.116,127.729 10.366,127.479 R4.1@10.366,126.779
NetR5_1: R5.1 U6.F15 | length 2.9
  Top Layer w0.2: R5.1@25.466,125.979 25.566,125.979 25.891,125.654 26.086,125.654 26.561,125.179 27.041,125.179 U6.F15@27.766,124.454
NetR6_2: R6.2 U6.J15 | length 1.8
  Top Layer w0.25: R6.2@29.016,125.979 29.716,125.279 U6.J15@29.716,124.454
NetR13_2: R13.2 SB12.2 U9.6 | length 12.8
  Top Layer w0.12: R13.2@11.125,119.325 11.125,118.775 11.251,118.649 13.321,118.649 v1(13.566,118.404) ; v1(14.691,111.704) U9.6@15.441,111.704
  Bottom Layer w0.12: v1(13.566,118.404) 13.566,116.679 13.571,116.674 13.571,114.504 14.691,113.384 v1(14.691,111.704) SB12.2@16.416,111.704
NetR18_1: R18.1 R19.1 U6.N3 | length 4.6
  Top Layer w0.15: U6.N3@32.316,116.654 32.646,116.324 33.099,116.324 33.286,116.137 33.286,115.881 33.484,115.684 34.296,115.684
  Top Layer w0.3: 34.296,115.684 34.751,115.229 R19.1@35.141,115.229
  Top Layer w0.45: R19.1@35.141,115.229 R18.1@35.141,116.279
NetR20_1: R20.1 X1.3 | length 1.2
  Top Layer w0.12: X1.3@28.416,111.729 R20.1@28.416,112.954
NetR20_2: R20.2 U6.G1 | length 1.5
  Top Layer w0.12: R20.2@28.416,113.854 U6.G1@28.416,115.354
NetR21_2: R21.2 U6.L4 | length 4.8
  Top Layer w0.15: U6.L4@31.016,117.304 31.341,116.979 31.794,116.979 31.991,116.782 31.991,115.829 32.146,115.674 32.449,115.674 32.636,115.487 32.636,115.034 32.791,114.879
  Top Layer w0.3: 32.791,114.879 33.191,114.479 R21.2@33.191,113.854
NetR22_1: R22.1 X1.1 | length 1.3
  Top Layer w0.3: X1.1@29.666,110.079 R22.1@30.916,110.079
NetR27_1: R27.1 R28.1 U12.A1 U12.C1 | length 4
  Top Layer w0.15: U12.C1@44.995,99.356 U12.A1@44.995,99.856
  Top Layer w0.2: R28.1@42.995,98.756 R27.1@42.995,100.156 43.995,100.156 44.295,99.856 U12.A1@44.995,99.856
NetR29_1: R29.1 U19.C3 | length 1.7
  Top Layer w0.25: R29.1@44.095,97.656 v1(44.095,98.656)
  Bottom Layer w0.25: v1(44.095,98.656) U19.C3@44.795,98.656
NetR40_2: R40.2 R41.2 U15.6 | length 4.3
  Top Layer w0.2: U15.6@36.47,11.456 36.47,10.017 36.07,9.617 R40.2@36.07,8.831 R41.2@37.57,8.831
NetR48_2: R48.2 SB14.1 U19.A2 U19.A3 | length 5.3
  Bottom Layer w0.2: R48.2@44.495,101.456 43.395,101.456 42.895,100.956 SB14.1@42.895,99.956 44.195,99.956 44.495,99.656 U19.A3@44.795,99.656 U19.A2@45.295,99.656
NetR49_1: R49.1 SB21.2 SB23.2 | length 24.8
  Top Layer w0.2: v1(37.781,93.281) v1(45.27,93.281)
  Bottom Layer w0.2: R49.1@35.57,101.281 35.57,99.505 37.775,97.3 v1@37.775,93.281 ; v1(45.27,93.281) 49.234,89.318 SB21.2@50.637,89.318 SB23.2@50.637,87.918
NetR52_2: R52.2 U19.A1 | length 2.2
  Bottom Layer w0.2: U19.A1@45.795,99.656 45.956,99.656 46.856,98.756 47.495,98.756 R52.2@47.595,98.656
NetSB14_2: SB14.2 SB15.2 U19.B3 | length 3.5
  Bottom Layer w0.25: SB15.2@41.395,98.856 SB14.2@42.895,98.856 43.195,99.156 U19.B3@44.795,99.156
NRST: B2.1 B2.2 C83.2 CN5.12 CN8.5 CN11.14 JP2.2 U13.25 U17.1 | length 178.8
  Top Layer w0.2: CN11.14@5.79,86.361 CN8.5@10.87,86.361 ; CN5.12@8.453,116.204 v1(10.441,116.204) ; v1(8.67,99.059) JP2.2@10.866,99.059 ; v1(38.337,58.394) U13.25@38.337,60.296 ; v1(39.87,19.181) 39.922,19.233 56.057,19.233 58.87,16.42 58.87,10.981 58.558,10.669 U17.1@57.67,10.669
  Top Layer w0.25: U17.1@57.67,10.669 57.67,8.562 B2.1@57.707,8.525 B2.2@67.207,8.525
  Signal Layer 2 w0.2: CN8.5@10.87,86.361 12.15,85.081 19.37,85.081 27.47,76.981 v1(38.87,76.981)
  Bottom Layer w0.2: v1(10.441,116.204) 10.441,108.179 8.67,106.408 v1(8.67,99.059) 8.67,87.081 9.39,86.361 CN8.5@10.87,86.361 ; C83.2@38.337,55.746 C83.2@38.337,55.804 ; v1(38.87,76.981) 38.87,72.72 36.418,70.268 36.418,69.033 40.37,65.081 40.37,62.295 40.075,62 39.075,62 38.525,61.45 38.525,58.582 v1(38.337,58.394) C83.2@38.337,55.804 ; v1(39.87,19.181) 39.87,19.681 37.37,22.181 37.37,35.765 36.87,36.265 36.87,40.854 36.17,41.554 36.17,52.594 36.77,53.194 36.77,54.945 37.525,55.7 38.233,55.7 C83.2@38.279,55.746 C83.2@38.337,55.804
OSC32_IN: C57.1 R32.2 X2.2 | length 2.9
  Top Layer w0.2: R32.2@29.287,54.577 29.6,54.577 C57.1@29.6,53.6 29.6,52.5 X2.2@29.475,52.375
  Top Layer w0.25: R32.2@28.97,54.577 R32.2@29.287,54.577
OSC32_OUT: C58.1 R33.2 X2.1 | length 2.8
  Top Layer w0.2: X2.1@30.575,52.375 30.475,52.475 C58.1@30.475,53.6 30.475,54.57 R33.2@30.786,54.57
  Top Layer w0.25: R33.2@30.786,54.57 31.036,54.57 R33.2@31.07,54.536
OSC_IN: C59.1 SB4.2 X3.1 | length 7.8
  Top Layer w0.2: C59.1@35.67,51.681 35.645,51.706 35.62,51.731 34.42,51.731 34.07,52.081 34.07,53.781 34.77,54.481 36.77,54.481 ; C59.1@35.67,51.731 X3.1@36.732,51.731 ; X3.1@36.842,51.621 X3.1@36.732,51.731 ; X3.1@36.87,51.681 36.82,51.731 X3.1@36.732,51.731
OSC_OUT: C60.1 SB5.2 X3.3 | length 3.1
  Top Layer w0.2: SB5.2@38.279,54.696 38.279,52.758 X3.3@38.192,52.671 39.26,52.671 C60.1@39.27,52.681
PA0: CN11.28 SB59.2 SB60.1 U13.33 | length 62.8
  Top Layer w0.2: U13.33@42.337,60.296 42.337,59.266 42.678,58.925 v1(42.95,58.925)
  Signal Layer 2 w0.2: CN11.28@5.79,68.581 7.07,68.581 9.37,70.881 16.27,70.881 18.17,68.981 v1(21.37,68.981) ; v1(17.27,56.781) v1(24.67,56.781) 25.571,57.681 42.681,57.681 42.95,57.95 v1(42.95,58.925)
  Bottom Layer w0.2: v1(17.27,56.781) 17.27,58.381 20.17,61.281 20.17,63.495 21.37,64.695 v1(21.37,68.981) ; SB60.1@23.17,55.581 23.27,55.681 SB59.2@24.67,55.681 v1(24.67,56.781)
PA1: CN10.11 CN11.30 U13.34 | length 60
  Top Layer w0.2: U13.34@42.837,60.296 v1(42.837,61.648)
  Signal Layer 2 w0.2: CN11.30@5.79,66.041 8.33,66.041 9.555,67.266 14.685,67.266 16.57,65.381 19.219,65.381 21.05,63.55 27.05,63.55 29.381,65.881 v1(43.07,65.881) ; v1(42.837,61.648) 43.524,60.961 CN10.11@56.59,60.961
  Bottom Layer w0.2: v1(42.837,61.648) 43.07,61.881 v1(43.07,65.881)
PA2: CN12.35 SB56.1 SB57.1 U13.35 | length 28.4
  Top Layer w0.127: U13.35@43.337,60.296 43.337,59.213 44.315,58.235 45.416,58.235 46.37,57.281 v1(46.37,56.681) v1(47.87,56.681) 47.87,58.881 48.17,59.181 55.145,59.181 55.645,59.681 62.925,59.681 CN12.35@64.21,58.396
  Bottom Layer w0.127: 46.37,55.681 v1(46.37,56.681) ; SB56.1@47.87,55.681 v1(47.87,56.681)
PA3: CN9.1 CN12.37 U13.36 | length 68.6
  Top Layer w0.2: U13.36@43.937,60.296 43.937,59.038 44.175,58.8 v1(44.875,58.8) ; v1(53.47,57.181) 59.97,57.181 61.295,55.856 CN12.37@64.21,55.856
  Signal Layer 2 w0.2: v1(10.87,70.381) 15.269,70.381 20.75,64.9 26.15,64.9 28.131,66.881 42.733,66.881 v1(43.733,65.881) ; v1(44.875,58.8) 51.851,58.8 v1(53.47,57.181)
  Bottom Layer w0.2: CN9.1@10.87,68.581 v1(10.87,70.381) ; v1(43.733,65.881) 43.733,61.589 43.806,61.516 43.811,61.516 44.025,61.303 44.025,61.297 44.286,61.036 44.291,61.036 44.875,60.453 v1(44.875,58.8)
PA4: CN11.32 SB35.1 SB38.1 U13.39 | length 74.5
  Top Layer w0.2: U13.39@45.937,63.371 v1(47.839,63.371)
  Signal Layer 2 w0.2: CN11.32@5.79,63.501 7.105,62.186 13.917,62.186 13.922,62.181 23.294,62.181 24.034,61.441 29.485,61.441 30.725,62.681 38.07,62.681 39.17,63.781 47.429,63.781 v1(47.839,63.371) ; v1(49.637,86.518) 51.134,86.518 52.27,85.381 v1(52.27,81.281)
  Bottom Layer w0.2: v1(47.839,63.371) 48.822,64.354 48.822,69.404 48.47,69.756 48.47,76.181 49.27,76.981 49.27,78.581 51.07,80.381 51.77,80.381 SB38.1@51.97,80.181 ; v1(49.637,86.518) SB35.1@50.737,86.518 ; 52.27,80.681 v1(52.27,81.281)
PA5: CN7.10 CN12.11 SB23.1 U13.40 | length 62.9
  Top Layer w0.2: v1(39.57,69.981) 39.57,65.181 40.88,63.871 U13.40@45.912,63.871 ; v1(39.625,80.525) 39.625,79.6 39.77,79.455 v1(39.77,78.781) ; CN7.10@59.13,90.425 60.926,90.425 62.475,88.876 CN12.11@64.21,88.876
  Signal Layer 2 w0.2: v1(43.97,84.981) 46.07,84.981 52.829,91.74 57.815,91.74 CN7.10@59.13,90.425
  Bottom Layer w0.2: v1(39.57,69.981) 39.57,75.881 39.922,76.233 39.922,76.668 39.77,76.82 v1(39.77,78.781) ; v1(39.625,80.525) 39.625,81.209 41.837,83.421 42.649,83.421 42.97,83.742 42.97,83.981 v1(43.97,84.981) ; SB23.1@51.737,87.918 52,88.181 52.614,88.181 56.114,91.681 57.874,91.681 CN7.10@59.13,90.425
PA6: CN7.12 CN12.13 U13.41 | length 50.2
  Top Layer w0.2: v1(40.17,70.381) 40.17,65.281 41.08,64.371 U13.41@45.912,64.371 ; v1(40.37,78.181) v1(40.37,80.481) ; v1(43.97,83.981) 45.07,83.981 46.77,85.681 51.609,85.681 55.109,89.181 57.834,89.181 CN7.12@59.13,87.885 61.166,87.885 62.715,86.336 CN12.13@64.21,86.336
  Bottom Layer w0.2: v1(40.17,70.381) 40.17,76.019 40.37,76.219 v1(40.37,78.181) ; v1(40.37,80.481) 40.37,80.754 42.71,83.094 43.083,83.094 v1(43.97,83.981)
PA7: CN7.14 CN12.15 U13.42 | length 47.3
  Top Layer w0.2: v1(40.87,70.981) 40.87,65.481 41.48,64.871 U13.42@45.912,64.871 ; v1(41.77,78.381) v1(41.77,80.481) ; v1(43.97,83.281) 44.234,83.546 45.37,83.546 46.47,84.646 51.234,84.646 53.17,86.581 57.894,86.581 CN7.14@59.13,85.345 61.006,85.345 62.555,83.796 CN12.15@64.21,83.796
  Bottom Layer w0.2: v1(40.87,70.981) 40.67,71.181 40.67,75.781 41.77,76.881 v1(41.77,78.381) ; v1(41.77,80.481) 41.77,81.081 v1(43.97,83.281)
PA8: CN10.31 CN12.23 U13.100 | length 94.3
  Top Layer w0.2: v1(30.337,78.781) U13.100@30.337,81.946 ; CN10.31@56.59,35.561 57.87,34.281 v1(62.73,34.281)
  Signal Layer 2 w0.2: v1(30.337,78.781) 38.009,78.781 43.418,73.372 43.418,72.934 44.2,72.152 46.541,72.152 46.791,72.402 51.191,72.402 51.39,72.601 51.95,72.601 52.149,72.402 62.976,72.402 CN12.23@64.21,73.636
  Signal Layer 3 w0.2: v1(62.73,34.281) 62.73,46.181 62.27,46.641 62.27,47.281 62.67,47.681 62.67,53.781 63.52,54.631 67.72,54.631 68.07,54.981 68.07,69.181 67.47,69.781 66.07,69.781 65.525,70.326 65.525,72.321 CN12.23@64.21,73.636
PA9: CN12.21 SB31.1 SB32.1 U13.101 | length 47.4
  Top Layer w0.2: U13.101@29.837,81.971 v1(29.837,83.375)
  Signal Layer 2 w0.2: v1(29.837,83.375) 29.837,80.614 31.051,79.4 38.151,79.4 42.67,74.881 48.87,74.881 50.07,73.681 53.77,73.681 55.77,75.681 57.97,75.681 58.44,76.151 58.44,76.176 CN12.21@64.21,76.176
  Bottom Layer w0.12: SB32.1@27.8,86.6 SB31.1@29.3,86.6 29.575,86.325 29.575,85.462 29.837,85.2 v1(29.837,83.375)
PA10: CN12.33 SB33.1 SB34.1 U13.102 | length 66.4
  Top Layer w0.2: U13.102@29.337,81.946 29.337,85.048 29.337,85.055 v1(29.344,85.048)
  Signal Layer 2 w0.12: v1(30.27,65.381) 46.97,65.381 48.57,63.781 52.97,63.781 54.475,62.276 62.87,62.276 CN12.33@64.21,60.936
  Bottom Layer w0.12: SB34.1@24.8,86.6 SB33.1@26.3,86.6 26.3,86.4 27.652,85.048 v1(29.344,85.048) 29.344,82.279 29.337,82.272 29.337,81.048 27.97,79.681 27.47,79.681 27.07,79.281 27.07,73.581 30.07,70.581 30.07,65.581 v1(30.27,65.381)
PA11: CN12.14 SB40.1 | length 43.4
  Bottom Layer w0.155: SB40.1@29.37,78.081 28.811,78.641 28.811,79.381 29.111,79.681 30.57,79.681 30.851,79.4 47.428,79.4 50.009,81.981 53.041,81.981 53.67,82.611 55.084,82.611 56.092,81.603 60.316,81.603 63.712,84.999 65.413,84.999 CN12.14@66.75,86.336
PA12: CN12.12 SB41.1 | length 45.9
  Bottom Layer w0.155: SB41.1@27.87,78.081 28.43,78.641 28.43,79.539 28.953,80.062 30.728,80.062 31.009,79.781 47.27,79.781 49.87,82.381 52.858,82.381 53.37,82.893 54.977,82.893 56.092,84.008 59.628,84.008 60.474,83.162 61.188,83.162 63.008,84.982 63.008,86.834 63.712,87.539 65.413,87.539 CN12.12@66.75,88.876
PA13: CN5.4 CN11.13 R11.1 U7.5 U13.105 | length 87.7
  Top Layer w0.12: v1(6.805,110.77) 7.995,111.96 13.287,111.96 14.737,113.41 15.451,113.41 15.926,112.935 17.42,112.935 v1(17.83,113.345) ; CN5.4@8.453,121.284 11.105,121.284 11.675,121.854 14.541,121.854 15.091,121.304 U7.5@15.466,121.304 16.904,121.304 R11.1@16.925,121.325 17.075,121.475 17.075,122.02 v1@17.075,122.025
  Top Layer w0.2: CN11.13@3.25,86.361 4.565,87.676 20.275,87.676 v1(22.97,84.981) 23.576,84.375 25.349,84.375 25.5,84.526 26.749,84.526 27.837,83.438 U13.105@27.837,81.971
  Bottom Layer w0.12: CN11.13@3.25,86.361 1.65,87.961 1.65,103.85 4.05,106.25 5.45,106.25 6.8,107.6 6.8,110.77 v1@6.8,110.775 ; v1(17.08,122.02) 17.625,121.475 17.625,113.55 v1@17.825,113.35
PA14: CN5.6 CN11.15 R12.2 U7.4 U13.109 | length 83.6
  Top Layer w0.12: v1(6.355,111.295) 7.26,112.2 13.188,112.2 14.638,113.65 15.55,113.65 16.025,113.175 16.585,113.175 v1(16.88,113.47) ; CN5.6@8.453,120.014 10.111,120.014 10.487,119.638 10.487,118.787 10.866,118.409 12.609,118.409 13.019,117.999 13.734,117.999 14.236,118.501 14.236,119.174 15.066,120.004 U7.4@15.466,120.004 16.921,120.004 R12.2@16.95,119.975 17.1,119.825 17.1,119.28 v1@17.1,119.275
  Top Layer w0.2: CN11.15@3.25,83.821 4.49,82.581 v1(17.17,82.581) ; v1(22.335,79.971) U13.109@24.237,79.971
  Signal Layer 2 w0.2: v1(17.17,82.581) 19.725,82.581 v1(22.335,79.971)
  Bottom Layer w0.12: CN11.15@3.25,83.821 1.275,85.796 1.275,104.075 3.875,106.675 5.3,106.675 6.35,107.725 6.35,111.295 v1@6.35,111.3 ; v1@16.875,113.475 17.375,113.975 17.375,114.78 17.105,115.05 v1(17.105,119.28)
PA15: CN11.17 SB39.2 SB42.2 U13.110 | length 25.5
  Top Layer w0.2: CN11.17@3.25,81.281 4.475,80.056 6.395,80.056 8.97,77.481 15.77,77.481 16.07,77.781 v1(17.17,77.781) ; v1(20.45,80.3) 21.379,79.371 U13.110@24.262,79.371
  Bottom Layer w0.2: v1(17.17,77.781) 18.531,77.781 SB42.2@18.7,77.95 SB39.2@18.7,79.371 18.7,80.2 18.8,80.3 v1(20.45,80.3)
PB0: SB63.1 SB64.1 SB65.2 U13.43 | length 28.5
  Top Layer w0.127: U13.43@45.937,65.371 v1(47.839,65.371)
  Bottom Layer w0.127: SB65.2@41.47,48.181 41.57,48.081 SB64.1@42.97,48.081 SB63.1@44.47,48.081 46.6,48.081 46.698,47.983 46.698,46.552 46.9,46.35 47.125,46.35 47.27,46.495 47.27,56.983 47.423,57.137 47.423,64.956 v1(47.839,65.371)
PB1: CN10.7 CN12.24 U13.44 | length 29.2
  Top Layer w0.2: U13.44@45.912,65.871 56.42,65.871 CN10.7@56.59,66.041
  Signal Layer 2 w0.2: CN10.7@56.59,66.041 57.21,66.041 58.47,64.781 v1(60.67,64.781) ; v1(60.67,71.781) 62.99,71.781 63.59,72.381 65.495,72.381 CN12.24@66.75,73.636
  Bottom Layer w0.2: v1(60.67,64.781) v1(60.67,71.781)
PB2: CN9.13 CN12.22 U13.45 | length 83.8
  Top Layer w0.2: v1(44.67,66.381) 45.912,66.381 45.927,66.381 U13.45@45.937,66.371
  Signal Layer 2 w0.2: CN9.13@10.87,53.341 12.13,52.081 14.37,52.081 16.27,50.181 40.37,50.181 v1(41.87,51.681) ; v1(43.87,73.181) 44.77,73.181 45.222,72.729 50.818,72.729 51.27,73.181 53.97,73.181 55.675,74.886 65.46,74.886 CN12.22@66.75,76.176
  Bottom Layer w0.2: v1(41.87,51.681) 41.87,53.92 43.111,55.161 44.086,55.161 44.825,55.9 44.825,57.765 45.086,58.026 45.101,58.026 45.97,58.895 45.97,65.081 v1(44.67,66.381) 43.77,67.281 43.77,69.681 44.27,70.181 44.27,71.581 43.879,71.972 43.87,71.962 v1(43.87,73.181)
PB3: CN7.15 CN12.31 SB44.2 U13.132 | length 72.6
  Top Layer w0.2: v1(20.87,68.381) 24.252,68.381 U13.132@24.262,68.371 ; CN7.15@56.59,82.805 57.84,81.555 62.644,81.555 v1(62.67,81.581)
  Signal Layer 2 w0.2: v1(20.87,68.381) 25.95,68.381 26.15,68.581 43.07,68.581 43.77,69.281 44.67,69.281 45.17,68.781 48.07,68.781 48.67,69.381 54.67,69.381 55.095,69.806 v1(62.67,69.806)
  Bottom Layer w0.2: 19.86,68.371 19.87,68.381 v1(20.87,68.381) ; v1(62.67,81.581) v1(62.67,69.806) 62.67,65.016 CN12.31@64.21,63.476
PB4: CN12.27 SB36.1 SB43.1 U13.133 | length 62.8
  Top Layer w0.2: U13.133@24.262,67.871 v1(26.139,67.871) ; v1(53.37,68.081) 54.114,67.337 60.026,67.337 61.245,68.556 CN12.27@64.21,68.556
  Signal Layer 2 w0.2: v1(26.139,67.871) 26.349,68.081 v1(53.37,68.081) ; v1(49.637,85.118) 50.98,85.118 51.57,84.527 51.57,80.831 53.37,79.031 v1(53.37,75.981)
  Bottom Layer w0.127: CN12.27@64.21,68.556 CN12.27@64.21,68.607
  Bottom Layer w0.2: v1(49.637,85.118) SB36.1@50.737,85.118 ; SB43.1@51.97,75.981 v1(53.37,75.981) v1(53.37,68.081)
PB5: CN12.29 SB37.1 SB46.2 U13.134 | length 74.9
  Top Layer w0.2: U13.134@24.262,67.371 v1(27.344,67.371) ; v1(54.07,84.081) 59.866,84.081 v1(61.718,82.229)
  Signal Layer 2 w0.2: v1(20.9,65.425) 24.525,65.425 26.471,67.371 v1(27.344,67.371) 43.68,67.371 44.18,66.871 48.355,66.871 48.821,67.337 v1(61.718,67.337) 62.889,67.337 CN12.29@64.21,66.016
  Bottom Layer w0.2: SB46.2@19.9,65.425 v1(20.9,65.425) ; SB37.1@51.737,83.718 52.083,83.718 52.447,84.081 v1(54.07,84.081) ; v1(61.718,67.337) v1(61.718,82.229)
PB6: CN9.15 CN12.17 U13.135 | length 99.7
  Top Layer w0.2: CN9.15@10.87,50.801 12.15,52.081 v1(18.37,52.081) ; v1(22.335,66.871) U13.135@24.237,66.871
  Signal Layer 2 w0.2: v1(24.987,84.946) 25.534,85.493 31.008,85.493 35.28,81.221 44.27,81.221 45.541,79.95 50.089,79.95 51.82,78.219 51.82,75.931 52.37,75.381 53.409,75.381 54.422,76.394 54.422,81.333 54.644,81.555 61.096,81.555 61.522,81.129 64.21,81.129 CN12.17@64.21,81.256
  Bottom Layer w0.2: v1(18.37,52.081) 18.37,57.981 21.17,60.781 21.17,63.295 22.335,64.46 v1(22.335,66.871) 22.87,67.406 22.87,69.281 22.47,69.681 20.77,69.681 20.47,69.981 20.47,72.481 20.97,72.981 21.67,72.981 24.987,76.298 v1(24.987,84.946)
